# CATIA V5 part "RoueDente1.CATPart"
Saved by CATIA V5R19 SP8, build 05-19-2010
Part number: pignon
Source: Unknown
Publications: "Esquisse.8", "Plan.3"
Material "Rouge DS": density 7860 kg/m3, Young's modulus 2e+11 Pa, Poisson ratio 0.266
Bounding box of the stored display mesh (mm): x 0 to 15, y -40.499 to 40.499, z -40.499 to 40.499
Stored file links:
  E:\EDELI\gcausse\Edeli_2012_190_gcausse\RoueDente1.CATPart
  C:\usr\gt1\projet\site_web\doc\catia\gears\spur_gear_files\parts\gear_n.CATPart
  C:\Users\thinkmotion1\Desktop\Nouveau dossier\Cremai_Automobile\Cremaillere_automobile.CATProduct
  C:\Program Files\Dassault Systemes\B20\win_b64\startup\materials\French\Catalog.CATMaterial
  C:\Program Files\Dassault Systemes\B20\win_b64\startup\materials\red_env_512x512.jpg
  E:\EDELI\gcausse\Edeli_2012_190_gcausse\Vol3_190.CATProduct
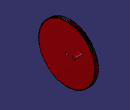
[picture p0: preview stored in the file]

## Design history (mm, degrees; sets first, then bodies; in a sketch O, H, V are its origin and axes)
Parameters
  a = 20 deg
  m = 0.5 mm
  Z = 160
  rp = 40 mm {= m * Z / 2}
  ra = 40.5 mm {= rp + m}
  rb = 37.5877 mm {= rp * cos( a )}
  rf = 39.375 mm {= rp - 1.25 * m}
  rc = 0.19 mm {= m * 0.38}
  c = 0.115855 {= sqrt( 1 / ( cos( a ) * cos( a ) ) - 1 ) / PI}
  phi = 1.4165 deg
  `diametre perçages extérieurs` = 35 mm
Set1
  DatumCurve1: linked copy from another document
Set2
  Line1 "Axe X": stored without definition
  Plane1: type Angle, RefPlane zx-plane, Direction Line1, Angle 1.125 {= 180deg / Z}
  Point1 "origine": (0, 0, 0)
  Point2: (0, 0, 37.5877)
  Point3: (0, 0.3847, 39.3971)
  Point4: (0, 2.9869, 44.2908)
  Point5: (0, 9.5865, 50.7534)
  Point6: (0, 21.1519, 56.5375)
  Curve1: Elements (Point2; Point3; Point4; Point5; Point6)
  Extrapol1: ToExtrapol Point2, Support Curve1, Length 1 {= m * 2}
  Rotate1: ToTransfor Extrapol1, Axis Line1, Angle 1.4165 {= phi}
  Circle1: type CtrRad, Start 0, End 180, Center Point1, Support yz-plane, Radius 39.375 {= rf}, FirstDirection (0, 1, 0)
  Circle2: type CtrRad, Start 0, End 180, Center Point1, Support yz-plane, Radius 40.5 {= ra}, FirstDirection (0, 1, 0)
  Corner1: Element1 Rotate1, Element2 Circle1, Radius 0.19 {= rc}
  Symmetry1: ToTransfor Corner1, Reference Plane1
  Split1: ToCut Rotate1, Cutting (Corner1; Circle2)
  Symmetry2: ToTransfor Split1, Reference zx-plane
  Circle3: type 2PointsRad, Start 0, End 180, FirstPoint vertex of Symmetry1, SecondPoint vertex of Corner1, Support yz-plane, Radius 39.375 {= rf}
  Circle4: type 2PointsRad, Start 0, End 180, FirstPoint vertex of Split1, SecondPoint vertex of Symmetry2, Support yz-plane, Radius 40.5 {= ra}
  Join1: Elements (Symmetry1; Circle3; Corner1; Split1; Circle4; Symmetry2)
  CircPattern1: of Join1, instances 160 {= Z}, angular step 2.25 {= 360.0*1 deg/CircPattern1.AngularNumber}, axis from Line1
  Join2: Elements (Join1; CircPattern1)
  Plane2: type Offset, RefPlane yz-plane, Offset 33
  Sketch1 on end face of Pad1, origin (5, 0, 0), H (0, 1, 0), V (0, 0, 1)
    circle A1 centre (0, 0) radius 2.5
    radius A1 = 2.5
Body1 (main body)
  Pad1: profile Join2, length 5
  Sketch2 on Plane2, origin (33, 0, 0), H (0, 1, 0), V (0, 0, 1)
    circle A1 centre (0, 0) radius 31.6677
    radius A1 = 31.6677
  Sketch3 on start face of Pad1, origin (0, 0, 0), H (0, -1, 0), V (0, 0, 1)
    circle A1 centre (0, 0) radius 10
    radius A1 = 10
  Sketch4 on end face of Pad1, origin (5, 0, 0), H (0, 1, 0), V (0, 0, 1)
    circle A1 centre (0, 0) radius 10
    radius A1 = 10
  Pocket1: profile Sketch1, direction (-1, 0, 0), length 5
  Sketch5 on end face of Pad1, origin (5, 0, 0), H (0, 1, 0), V (0, 0, 1)
    circle A1 centre (20, 10) radius 2.5
    radius A1 = 2.5
  Pad2: profile Sketch5, direction (1, 0, 0), length 10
